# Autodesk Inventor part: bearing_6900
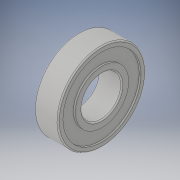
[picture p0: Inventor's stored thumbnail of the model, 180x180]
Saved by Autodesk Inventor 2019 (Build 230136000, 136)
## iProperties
Created: 2022-11
Part Number: bearing_6900
Material: Generic
Catalog Web Link: www.cadenas.de
Description: 6000_bearing-Deep Groove Ball Bearings
Vendor: MISUMI
Document SubType Name: Modeling
Designer: psAdmin
Manufacturer: MISUMI
Mass: 1.66105 g
Surface Area: 12.7379 cm^2
Volume: 1.66105 cm^3
Density: 1 g/cm^3
Appearance: PSOLRGB-175-175-175
Category: PARTsolutions
Company: MISUMI
Title: bearing_6900
Author: Cadenas PARTsolutions
Comments: Deep Groove Ball Bearings
PSOL_IDENT_0: {$CADENAS_DATA/23d-libs/misumi/metric/accessories/bearing_6000.prj},170 {VTYP=3D},{NB=bearing_6900},
PSOL_IDENT_1: {LINA=bearing_6900},{NN=6000_bearing},{DATE=30.06.2021 13:30:08},{GEOMDATE=24.10.2013 00:00:00},{VER
PSOL_IDENT_2: SION=},{LINEID=30},{WBVAR=},{WBNUMERIC=}  {NB=bearing_6900},{LINA=bearing_6900},{KT=DUMMY},{PN=beari
PSOL_IDENT_3: ng_6900},{BN=6900},{DD=10},{D=22},{B=6},{RR=0.3},{DSMIN=12.0},{DS1=13.00},{DSMAX=13.00},{DDHH=20.0},
PSOL_IDENT_4: {R=0.3},{R1=0.200},{R2=0.300},{MASS=9},{MASS11=9},{AA=5.1000},{BB=1.2000},{CC=1.7000},{DD1=20.800}
NB: bearing_6900
NN: 6000_bearing
NT: Deep Groove Ball Bearings
NBSYN: $PN.
LINA: bearing_6900
CATALOG: Misumi
PN: bearing_6900
BN: 6900
DD: 10
D: 22
B: 6
RR: 0.3
DSMIN: 12
DDHH: 20
R: 0.3
MASS11: 9
SUPPLIER: MISUMI
ARTICLENO: bearing_6900
BOMINFO: bearing_6900
CREATOR: CADENAS GmbH
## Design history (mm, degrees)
sketch "Sketch_1"
  geometry: L1 (6, 0)-(0, 0); L2 (0.3, 5)-(5.7, 5); L3 (6, 5.3)-(6, 6.7); L4 (6, 6.7)-(5.55, 6.7); L5 (5.55, 6.7)-(5.55, 9.8); L6 (5.55, 9.8)-(6, 9.8); L7 (6, 9.8)-(6, 10.7); L8 (5.7, 11)-(0.3, 11); L9 (0, 10.7)-(0, 9.8); L10 (0, 9.8)-(0.45, 9.8); L11 (0.45, 9.8)-(0.45, 6.7); L12 (0.45, 6.7)-(0, 6.7); L13 (0, 6.7)-(0, 5.3); A1 r 0.3 centre (0.3, 5.3) between (0, 5.3) and (0.3, 5); A2 r 0.3 centre (5.7, 5.3) between (5.7, 5) and (6, 5.3); A3 r 0.3 centre (5.7, 10.7) between (6, 10.7) and (5.7, 11); A4 r 0.3 centre (0.3, 10.7) between (0.3, 11) and (0, 10.7)
  constraints: 26 end point, 8 point on circle, 4 centre point
revolve "Revolution1" sketch "Sketch_1" stored, may be unused: angle "d0" = 360 deg
node "center_point_XY"
node "center_point_YZ"
node "center_point_ZX"
node "center_point_X"
node "center_point_Y"
node "center_point_Z"
node "center_point_Center"
node "to_housing_XY"
node "to_housing_YZ"
node "to_housing_ZX"
node "to_housing_X"
node "to_housing_Y"
node "to_housing_Z"
node "to_housing_Center"
node "to_ring_XY"
node "to_ring_YZ"
node "to_ring_ZX"
node "to_ring_X"
node "to_ring_Y"
node "to_ring_Z"
node "to_ring_Center"
body "Solid1"
other parameters: "d1" = 0
